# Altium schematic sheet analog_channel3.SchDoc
size A4; SheetNumber: 4; SheetTotal: 6
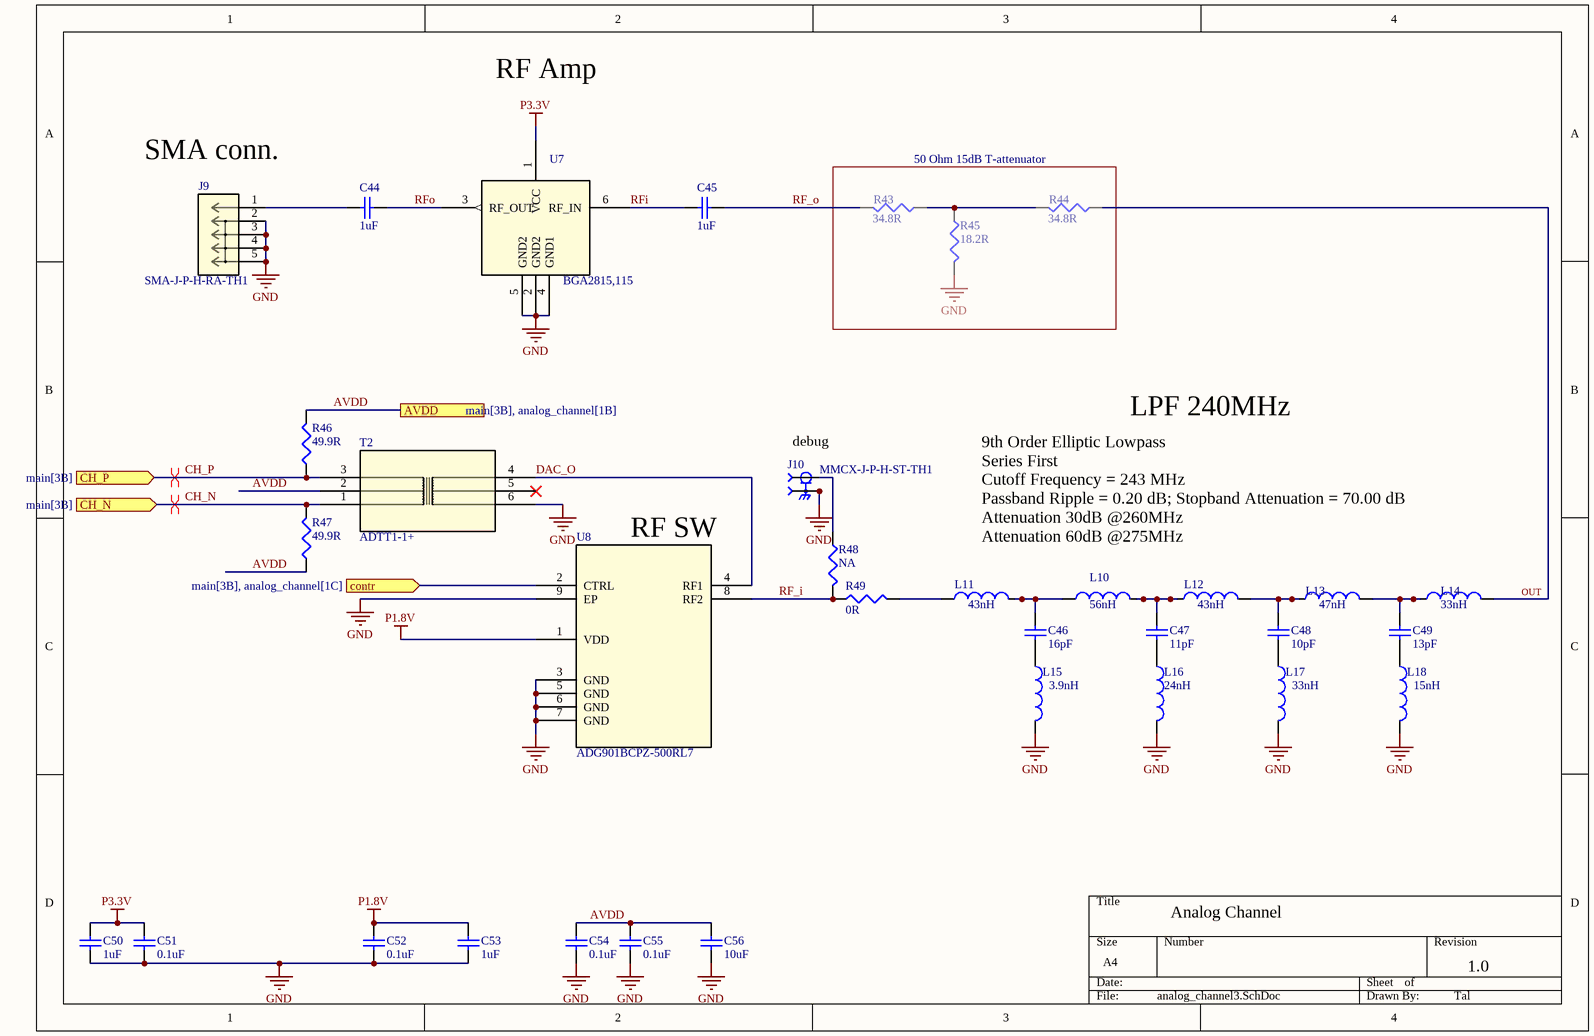
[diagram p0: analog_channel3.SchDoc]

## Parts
C44  Capacitance: 1uF  [c0402]  (hidden comment: 1uF 25V)
C45  Capacitance: 1uF  [c0402]  (hidden comment: 1uF 25V)
C46  Capacitance: 16pF  [c0402]  (hidden comment: 16pF 50V)
C47  Capacitance: 11pF  [c0402]  (hidden comment: 11pF 50V)
C48  Capacitance: 10pF  [c0402]  (hidden comment: 10pF 50V)
C49  Capacitance: 13pF  [c0402]  (hidden comment: 13pF 50V)
C50  Capacitance: 1uF  [c0402]  (hidden comment: 1uF 25V)
C51  Capacitance: 0.1uF  [c0402]  (hidden comment: 0.1uF 50V)
C52  Capacitance: 0.1uF  [c0402]  (hidden comment: 0.1uF 50V)
C53  Capacitance: 1uF  [c0402]  (hidden comment: 1uF 25V)
C54  Capacitance: 0.1uF  [c0402]  (hidden comment: 0.1uF 50V)
C55  Capacitance: 0.1uF  [c0402]  (hidden comment: 0.1uF 50V)
C56  Capacitance: 10uF  [c0402]  (hidden comment: 10uF 10V)
J9  SMA-J-P-H-RA-TH1  [CONN_SMA-J-P-H-RA-TH1_SAI]
J10  MMCX-J-P-H-ST-TH1  [SAMTEC_MMCX-J-P-H-ST-TH1]
L10  value 56nH  [0402-A]  (hidden comment: Inductor)
L11  value 43nH  [0402-A]  (hidden comment: Inductor)
L12  value 43nH  [0402-A]  (hidden comment: Inductor)
L13  value 47nH  [0402-A]  (hidden comment: Inductor)
L14  value 33nH  [0402-A]  (hidden comment: Inductor)
L15  value 3.9nH  [0402-A]  (hidden comment: Inductor)
L16  value 24nH  [0402-A]  (hidden comment: Inductor)
L17  value 33nH  [0402-A]  (hidden comment: Inductor)
L18  value 15nH  [0402-A]  (hidden comment: Inductor)
R43  34.8R  [r0402]
R44  34.8R  [r0402]
R45  18.2R  [r0402]
R46  49.9R  [r0402]
R47  49.9R  [r0402]
R48  NA  [r0402]
R49  0R  [r0402]
T2  ADTT1-1+  [CD542_MNC]
U7  BGA2815,115  [SOT_2815,115_NXP]
U8  ADG901BCPZ-500RL7  [CP_8_2_ADI]

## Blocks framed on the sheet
50 Ohm 15dB T-attenuator: R43-R45

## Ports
AVDD (see main[3B], analog_channel[1B]), CH_N (in, see main[3B]), CH_P (in, see main[3B]), contr (in, see main[3B], analog_channel[1C])

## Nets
GND: C50.1 C51.1 C52.1 C53.1 C54.1 C55.1 C56.1 J9.2 J9.3 J9.4 J9.5 J10.S1 J10.S2 J10.S3 J10.S4 L15.2 L16.2 L17.2 L18.2 R45.2 T2.6 U7.2(GND2) U7.4(GND1) U7.5(GND2) U8.3(GND) U8.5(GND) U8.6(GND) U8.7(GND) U8.9(EP)
P1.8V: C52.2 C53.2 U8.1(VDD)
P3.3V: C50.2 C51.2 U7.1(VCC)
AVDD: C54.2 C55.2 C56.2 R46.2 R47.1 T2.2 ; port AVDD
CH_N: R47.2 T2.1 ; port CH_N
CH_P: R46.1 T2.3 ; port CH_P
contr: U8.2(CTRL) ; port contr
DAC_O: T2.4 U8.4(RF1)
OUT: L14.2 R44.1
RF_i: R48.2 R49.1 U8.8(RF2)
RF_o: C45.2 R43.2
RFi: C45.1 U7.6(RF_IN)
RFo: C44.2 U7.3(RF_OUT)
NetC44_1: C44.1 J9.1
NetC46_1: C46.1 L10.1 L11.2
NetC46_2: C46.2 L15.1
NetC47_1: C47.1 L10.2 L12.1
NetC47_2: C47.2 L16.1
NetC48_1: C48.1 L12.2 L13.1
NetC48_2: C48.2 L17.1
NetC49_1: C49.1 L13.2 L14.1
NetC49_2: C49.2 L18.1
NetJ10_1: J10.1 R48.1
NetL11_1: L11.1 R49.2
NetR43_1: R43.1 R44.2 R45.1

Not connected (* = marked no-connect by the designer): T2 5*

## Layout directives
differential pair: CH_N, CH_P

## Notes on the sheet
- RF Amp
- (near J9) SMA conn.
- (near J10) debug
- LPF 240MHz
- (near U8) RF SW
- 9th Order Elliptic Lowpass
  Series First
  Cutoff Frequency = 243 MHz
  Passband Ripple = 0.20 dB; Stopband Attenuation = 70.00 dB
  Attenuation 30dB @260MHz
  Attenuation 60dB @275MHz
- Analog Channel
- 1.0
- Tal

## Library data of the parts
C44 C45 C50 C53 = CAP CER 6.8pF 50V NP0 0402: CAP CER 1uF 25V X5R 0402; Manufacturer Part Number: C1005C0G1H6R8D; Manufacturer: TDK Corporation; LANDA P/N: ECP-000033; Voltage - Rated: 50V
C46 = CAP CER 20pF 50V 5% NP0 0402: CAP CER 16PF 50V 5% NP0 0402; Manufacturer: TDK Corporation; Manufacturer Part Number: C1005C0G1H200J; LANDA P/N: ECP-000034
C47 = CAP CER 20pF 50V 5% NP0 0402: CAP CER 11PF 50V 5% NP0 0402; Manufacturer: TDK Corporation; Manufacturer Part Number: C1005C0G1H200J; LANDA P/N: ECP-000034
C48 = CAP CER 20pF 50V 5% NP0 0402: CAP CER 10PF 50V 5% NP0 0402; Manufacturer: TDK Corporation; Manufacturer Part Number: C1005C0G1H200J; LANDA P/N: ECP-000034
C49 = CAP CER 20pF 50V 5% NP0 0402: CAP CER 13PF 50V 5% NP0 0402; Manufacturer: TDK Corporation; Manufacturer Part Number: C1005C0G1H200J; LANDA P/N: ECP-000034
C51 C52 C54 C55 = CAP CER 6.8pF 50V NP0 0402: CAP CER 0.1uF 50V NP0 0402; Manufacturer Part Number: C1005C0G1H6R8D; Manufacturer: TDK Corporation; LANDA P/N: ECP-000033
C56 = CAP CER 6.8pF 50V NP0 0402: CAP CER 10uF 10V X5R 0402; Manufacturer Part Number: C1005C0G1H6R8D; Manufacturer: TDK Corporation; LANDA P/N: ECP-000033; Voltage - Rated: 50V
J9 = SMA-J-P-H-RA-TH1: No Description Available; Mfr_Name: Samtec Inc
J10 = MMCX-J-P-H-ST-TH1: MMCX STRAIGHT, THROUGH HOLE JACK- 50 OHM; MF: Samtec
L10-L18 = Inductor: Code_IEC: 1005
R43 R44 = RES 100 OHM 1/10W 1% 0402 SMD: RES 34.8 OHM 1/10W 1% 0402 SMD; Manufacturer Part Number: ERJ-2RKF1000X; Manufacturer: Panasonic Electronic Components; LANDA P/N: ERS-000079; Assembly: N.C
R45 = RES 100 OHM 1/10W 1% 0402 SMD: RES 18.2 OHM 1/10W 1% 0402 SMD; Manufacturer Part Number: ERJ-2RKF1000X; Manufacturer: Panasonic Electronic Components; LANDA P/N: ERS-000079; Assembly: N.C
R46 R47 = RES 100 OHM 1/10W 1% 0402 SMD: RES 49.9 OHM 1/10W 1% 0402 SMD; Manufacturer Part Number: ERJ-2RKF1000X; Manufacturer: Panasonic Electronic Components; LANDA P/N: ERS-000079; Assembly: N.C
R48 R49 = RES 100 OHM 1/10W 1% 0402 SMD: RES 0 OHM 1/10W 1% 0402 SMD; Manufacturer Part Number: ERJ-2RKF1000X; Manufacturer: Panasonic Electronic Components; LANDA P/N: ERS-000079; Assembly: N.C
T2 = ADTT1-1+: No Description Available; Mfr_Name: Mini Circuits; Type: DEV
U7 = BGA2815,115: No Description Available; Mfr_Name: NXP
U8 = ADG901BCPZ-500RL7: No Description Available; Mfr_Name: Analog Devices Inc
